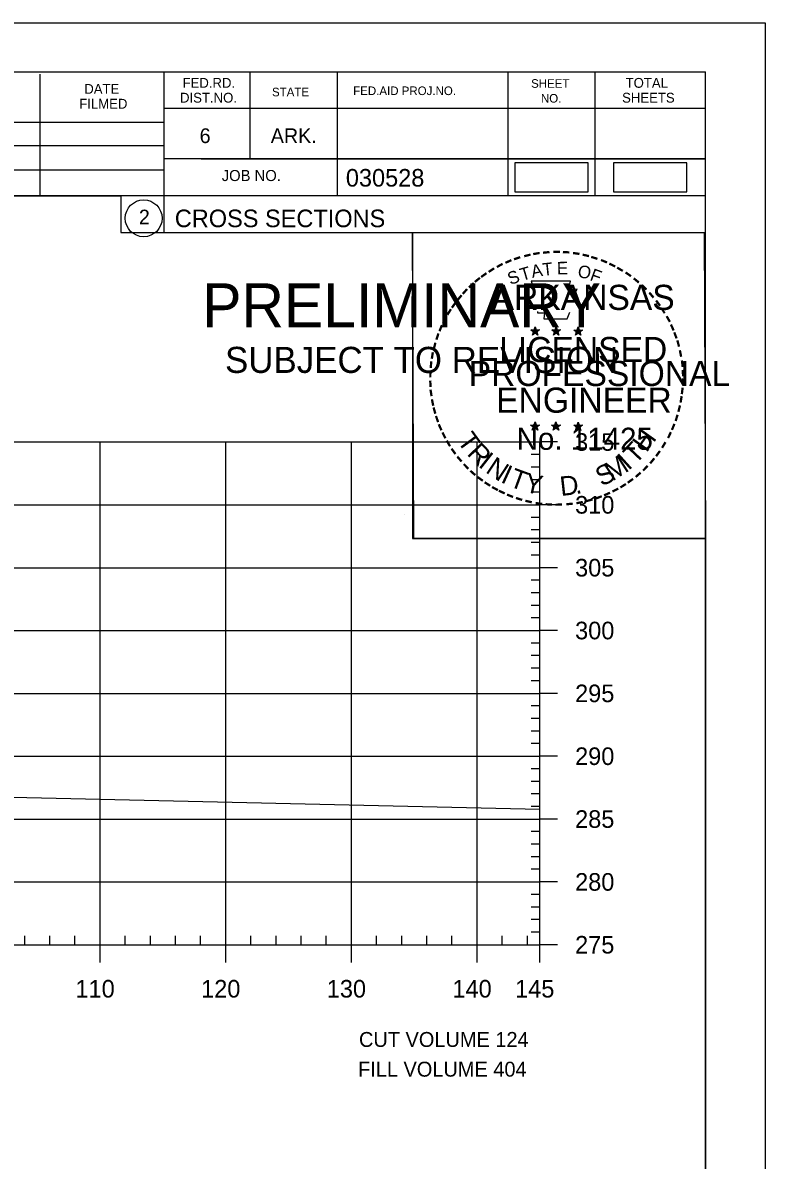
# Model space of a CAD drawing. Extents: x 1370843 to 1371177, y 380307 to 382654.
# Drawn here: x 1371117.6 to 1371176.6, y 380857 to 380947.5 of the extents above; entities that cross this region are included whole.
import ezdxf

# ---------------------------------------------------------------- set-up
doc = ezdxf.new("R2010")
doc.units = 0
for name, color, linetype in [('R_Axis', 7, 'Continuous'), ('R_Axis Annot', 7, 'Continuous'), ('R_Border', 7, 'Continuous'), ('R_Border Notes', 7, 'Continuous'), ('R_Border PE', 7, 'Continuous'), ('R_Border Prem', 7, 'Continuous'), ('R_Draft', 7, 'Continuous'), ('R_Exist Surface', 7, 'Continuous'), ('R_Grid', 7, 'Continuous'), ('R_No Plot', 7, 'Continuous')]:
    doc.layers.add(name, color=color, linetype=linetype)

msp = doc.modelspace()

# ---------------------------------------------------------------- linework, layer by layer
at = {"layer": 'R_Axis'}
for p, q in [((1371158.709, 380874.124), (1371158.709, 380914.124)), ((1371160.109, 380914.124), (1371158.709, 380914.124)), ((1371158.709, 380913.124), (1371158.009, 380913.124)), ((1371158.709, 380912.124), (1371158.009, 380912.124)), ((1371158.709, 380911.124), (1371158.009, 380911.124)), ((1371158.709, 380910.124), (1371158.009, 380910.124)), ((1371160.109, 380909.124), (1371158.709, 380909.124)), ((1371158.709, 380908.124), (1371158.009, 380908.124)), ((1371158.709, 380907.124), (1371158.009, 380907.124)), ((1371158.709, 380906.124), (1371158.009, 380906.124)), ((1371158.709, 380905.124), (1371158.009, 380905.124)), ((1371160.109, 380904.124), (1371158.709, 380904.124)), ((1371158.709, 380903.124), (1371158.009, 380903.124)), ((1371158.709, 380902.124), (1371158.009, 380902.124)), ((1371158.709, 380901.124), (1371158.009, 380901.124)), ((1371158.709, 380900.124), (1371158.009, 380900.124)), ((1371160.109, 380899.124), (1371158.709, 380899.124)), ((1371158.709, 380898.124), (1371158.009, 380898.124)), ((1371158.709, 380897.124), (1371158.009, 380897.124)), ((1371158.709, 380896.124), (1371158.009, 380896.124)), ((1371158.709, 380895.124), (1371158.009, 380895.124)), ((1371160.109, 380894.124), (1371158.709, 380894.124)), ((1371158.709, 380893.124), (1371158.009, 380893.124)), ((1371158.709, 380892.124), (1371158.009, 380892.124)), ((1371158.709, 380891.124), (1371158.009, 380891.124)), ((1371158.709, 380890.124), (1371158.009, 380890.124)), ((1371160.109, 380889.124), (1371158.709, 380889.124)), ((1371158.709, 380888.124), (1371158.009, 380888.124)), ((1371158.709, 380887.124), (1371158.009, 380887.124)), ((1371158.709, 380886.124), (1371158.009, 380886.124)), ((1371158.709, 380885.124), (1371158.009, 380885.124)), ((1371160.109, 380884.124), (1371158.709, 380884.124)), ((1371158.709, 380883.124), (1371158.009, 380883.124)), ((1371158.709, 380882.124), (1371158.009, 380882.124)), ((1371158.709, 380881.124), (1371158.009, 380881.124)), ((1371158.709, 380880.124), (1371158.009, 380880.124)), ((1371160.109, 380879.124), (1371158.709, 380879.124)), ((1371158.709, 380878.124), (1371158.009, 380878.124)), ((1371158.709, 380877.124), (1371158.009, 380877.124)), ((1371158.709, 380876.124), (1371158.009, 380876.124)), ((1371117.709, 380874.124), (1371117.709, 380874.824)), ((1371119.709, 380874.124), (1371119.709, 380874.824)), ((1371121.709, 380874.124), (1371121.709, 380874.824)), ((1371125.709, 380874.124), (1371125.709, 380874.824)), ((1371127.709, 380874.124), (1371127.709, 380874.824)), ((1371129.709, 380874.124), (1371129.709, 380874.824)), ((1371131.709, 380874.124), (1371131.709, 380874.824)), ((1371135.709, 380874.124), (1371135.709, 380874.824)), ((1371137.709, 380874.124), (1371137.709, 380874.824)), ((1371139.709, 380874.124), (1371139.709, 380874.824)), ((1371141.709, 380874.124), (1371141.709, 380874.824)), ((1371145.709, 380874.124), (1371145.709, 380874.824)), ((1371147.709, 380874.124), (1371147.709, 380874.824)), ((1371149.709, 380874.124), (1371149.709, 380874.824)), ((1371151.709, 380874.124), (1371151.709, 380874.824)), ((1371155.709, 380874.124), (1371155.709, 380874.824)), ((1371157.709, 380874.124), (1371157.709, 380874.824)), ((1371158.709, 380875.124), (1371158.009, 380875.124)), ((1370868.709, 380874.124), (1371158.709, 380874.124)), ((1371123.709, 380872.724), (1371123.709, 380874.124)), ((1371133.709, 380872.724), (1371133.709, 380874.124)), ((1371143.709, 380872.724), (1371143.709, 380874.124)), ((1371153.709, 380872.724), (1371153.709, 380874.124)), ((1371158.709, 380872.724), (1371158.709, 380874.124)), ((1371160.109, 380874.124), (1371158.709, 380874.124))]:
    msp.add_line(p, q, dxfattribs=at)
at = {"layer": 'R_Border'}
for p, q in [((1370855.709, 380943.584), (1371171.889, 380943.584)), ((1371128.789, 380943.584), (1371128.789, 380930.784)), ((1371135.629, 380943.584), (1371135.629, 380936.644)), ((1371142.569, 380943.584), (1371142.569, 380933.704)), ((1371156.149, 380943.584), (1371156.149, 380933.704)), ((1371163.089, 380943.584), (1371163.089, 380933.704)), ((1371171.889, 380738.124), (1371171.889, 380943.584)), ((1371118.929, 380933.704), (1371118.929, 380943.384)), ((1371171.889, 380940.644), (1371128.789, 380940.644)), ((1371171.889, 380940.664), (1371171.889, 380940.664)), ((1371089.629, 380939.564), (1371128.789, 380939.564)), ((1371089.629, 380937.704), (1371128.789, 380937.704)), ((1371171.889, 380936.644), (1371128.789, 380936.644)), ((1371131.749, 380936.644), (1371171.889, 380936.644)), ((1371089.629, 380935.764), (1371128.789, 380935.764)), ((1371171.889, 380933.704), (1371089.629, 380933.704)), ((1371128.789, 380930.784), (1371171.889, 380930.784))]:
    msp.add_line(p, q, dxfattribs=at)
msp.add_circle((1371127.176, 380931.92), 1.467, dxfattribs=at)
at = {"layer": 'R_Border PE'}
for p, q in [((1371157.974, 380923.039), (1371158.323, 380922.928)), ((1371157.974, 380923.039), (1371158.227, 380922.994)), ((1371157.974, 380923.039), (1371158.211, 380922.917)), ((1371158.107, 380922.631), (1371158.323, 380922.928)), ((1371158.107, 380922.631), (1371158.233, 380922.875)), ((1371158.107, 380922.631), (1371158.321, 380922.848)), ((1371158.323, 380923.293), (1371158.282, 380923.041)), ((1371158.536, 380922.631), (1371158.321, 380922.845)), ((1371158.323, 380922.928), (1371158.323, 380923.293)), ((1371158.323, 380923.293), (1371158.372, 380923.043)), ((1371158.67, 380923.039), (1371158.323, 380922.928)), ((1371158.536, 380922.631), (1371158.323, 380922.928)), ((1371158.67, 380923.039), (1371158.384, 380922.99)), ((1371158.536, 380922.631), (1371158.399, 380922.922)), ((1371158.67, 380923.039), (1371158.466, 380922.937)), ((1371159.644, 380923.039), (1371159.993, 380922.928)), ((1371159.644, 380923.039), (1371159.897, 380922.994)), ((1371159.644, 380923.039), (1371159.881, 380922.917)), ((1371159.777, 380922.631), (1371159.993, 380922.928)), ((1371159.777, 380922.631), (1371159.903, 380922.875)), ((1371159.777, 380922.631), (1371159.991, 380922.848)), ((1371159.993, 380923.293), (1371159.952, 380923.041)), ((1371160.206, 380922.631), (1371159.991, 380922.845)), ((1371159.993, 380922.928), (1371159.993, 380923.293)), ((1371159.993, 380923.293), (1371160.042, 380923.043)), ((1371160.34, 380923.039), (1371159.993, 380922.928)), ((1371160.206, 380922.631), (1371159.993, 380922.928)), ((1371160.34, 380923.039), (1371160.054, 380922.99)), ((1371160.206, 380922.631), (1371160.069, 380922.922)), ((1371160.34, 380923.039), (1371160.136, 380922.937)), ((1371161.408, 380923.027), (1371161.757, 380922.916)), ((1371161.408, 380923.027), (1371161.661, 380922.982)), ((1371161.408, 380923.027), (1371161.645, 380922.905)), ((1371161.541, 380922.619), (1371161.757, 380922.916)), ((1371161.541, 380922.619), (1371161.667, 380922.863)), ((1371161.541, 380922.619), (1371161.755, 380922.836)), ((1371161.757, 380923.281), (1371161.716, 380923.029)), ((1371161.97, 380922.619), (1371161.755, 380922.833)), ((1371161.757, 380922.916), (1371161.757, 380923.281)), ((1371161.757, 380923.281), (1371161.806, 380923.031)), ((1371162.104, 380923.027), (1371161.757, 380922.916)), ((1371161.97, 380922.619), (1371161.757, 380922.916)), ((1371162.104, 380923.027), (1371161.818, 380922.978)), ((1371161.97, 380922.619), (1371161.833, 380922.91)), ((1371162.104, 380923.027), (1371161.9, 380922.925)), ((1371157.97, 380915.466), (1371158.319, 380915.355)), ((1371157.97, 380915.466), (1371158.223, 380915.421)), ((1371157.97, 380915.466), (1371158.207, 380915.344)), ((1371158.103, 380915.058), (1371158.319, 380915.355)), ((1371158.319, 380915.72), (1371158.278, 380915.468)), ((1371158.319, 380915.355), (1371158.319, 380915.72)), ((1371158.319, 380915.72), (1371158.368, 380915.47)), ((1371158.666, 380915.466), (1371158.319, 380915.355)), ((1371158.532, 380915.058), (1371158.319, 380915.355)), ((1371158.666, 380915.466), (1371158.38, 380915.417)), ((1371158.666, 380915.466), (1371158.462, 380915.364)), ((1371159.639, 380915.466), (1371159.988, 380915.355)), ((1371159.639, 380915.466), (1371159.892, 380915.421)), ((1371159.639, 380915.466), (1371159.876, 380915.344)), ((1371159.772, 380915.058), (1371159.988, 380915.355)), ((1371159.988, 380915.72), (1371159.947, 380915.468)), ((1371159.988, 380915.355), (1371159.988, 380915.72)), ((1371159.988, 380915.72), (1371160.037, 380915.47)), ((1371160.335, 380915.466), (1371159.988, 380915.355)), ((1371160.201, 380915.058), (1371159.988, 380915.355)), ((1371160.335, 380915.466), (1371160.049, 380915.417)), ((1371160.335, 380915.466), (1371160.131, 380915.364)), ((1371161.406, 380915.456), (1371161.755, 380915.345)), ((1371161.406, 380915.456), (1371161.659, 380915.411)), ((1371161.406, 380915.456), (1371161.643, 380915.334)), ((1371161.755, 380915.71), (1371161.714, 380915.458)), ((1371161.755, 380915.345), (1371161.755, 380915.71)), ((1371161.755, 380915.71), (1371161.804, 380915.46)), ((1371162.102, 380915.456), (1371161.755, 380915.345)), ((1371162.102, 380915.456), (1371161.816, 380915.407)), ((1371162.102, 380915.456), (1371161.898, 380915.354)), ((1371158.103, 380915.058), (1371158.229, 380915.302)), ((1371158.103, 380915.058), (1371158.317, 380915.275)), ((1371158.532, 380915.058), (1371158.317, 380915.272)), ((1371158.532, 380915.058), (1371158.395, 380915.349)), ((1371159.772, 380915.058), (1371159.898, 380915.302)), ((1371159.772, 380915.058), (1371159.986, 380915.275)), ((1371160.201, 380915.058), (1371159.986, 380915.272)), ((1371160.201, 380915.058), (1371160.064, 380915.349)), ((1371161.539, 380915.048), (1371161.755, 380915.345)), ((1371161.539, 380915.048), (1371161.665, 380915.292)), ((1371161.539, 380915.048), (1371161.753, 380915.265)), ((1371161.968, 380915.048), (1371161.753, 380915.262)), ((1371161.968, 380915.048), (1371161.755, 380915.345)), ((1371161.968, 380915.048), (1371161.831, 380915.339))]:
    msp.add_line(p, q, dxfattribs=at)
for points in [[(1371158.015, 380926.917), (1371158.284, 380926.09)], [(1371161.526, 380925.995), (1371161.668, 380926.279), (1371160.983, 380926.255), (1371161.131, 380926.917), (1371158.015, 380926.917)], [(1371158.507, 380924.494), (1371158.507, 380924.407), (1371159.07, 380924.388), (1371159.016, 380923.915), (1371160.886, 380923.915), (1371161.087, 380924.451)], [(1371158.323, 380923.293), (1371158.536, 380922.631), (1371157.974, 380923.039), (1371158.67, 380923.039), (1371158.107, 380922.631), (1371158.323, 380923.293)], [(1371159.993, 380923.293), (1371160.206, 380922.631), (1371159.644, 380923.039), (1371160.34, 380923.039), (1371159.777, 380922.631), (1371159.993, 380923.293)], [(1371161.757, 380923.281), (1371161.97, 380922.619), (1371161.408, 380923.027), (1371162.104, 380923.027), (1371161.541, 380922.619), (1371161.757, 380923.281)], [(1371158.319, 380915.72), (1371158.532, 380915.058), (1371157.97, 380915.466), (1371158.666, 380915.466), (1371158.103, 380915.058), (1371158.319, 380915.72)], [(1371159.988, 380915.72), (1371160.201, 380915.058), (1371159.639, 380915.466), (1371160.335, 380915.466), (1371159.772, 380915.058), (1371159.988, 380915.72)], [(1371161.755, 380915.71), (1371161.968, 380915.048), (1371161.406, 380915.456), (1371162.102, 380915.456), (1371161.539, 380915.048), (1371161.755, 380915.71)]]:
    msp.add_lwpolyline(points, dxfattribs=at)
for centre, radius in [((1371158.322, 380922.927), 0.172), ((1371158.322, 380922.927), 0.145), ((1371158.322, 380922.927), 0.116), ((1371158.322, 380922.927), 0.0991), ((1371158.322, 380922.927), 0.0747), ((1371158.322, 380922.927), 0.0495), ((1371158.322, 380922.927), 0.0296), ((1371159.992, 380922.927), 0.172), ((1371159.992, 380922.927), 0.145), ((1371159.992, 380922.927), 0.116), ((1371159.992, 380922.927), 0.0991), ((1371159.992, 380922.927), 0.0747), ((1371159.992, 380922.927), 0.0495), ((1371159.992, 380922.927), 0.0296), ((1371161.756, 380922.915), 0.172), ((1371161.756, 380922.915), 0.145), ((1371161.756, 380922.915), 0.116), ((1371161.756, 380922.915), 0.0991), ((1371161.756, 380922.915), 0.0747), ((1371161.756, 380922.915), 0.0495), ((1371161.756, 380922.915), 0.0296), ((1371158.318, 380915.354), 0.172), ((1371158.318, 380915.354), 0.145), ((1371158.318, 380915.354), 0.116), ((1371158.318, 380915.354), 0.0991), ((1371158.318, 380915.354), 0.0747), ((1371158.318, 380915.354), 0.0495), ((1371158.318, 380915.354), 0.0296), ((1371159.987, 380915.354), 0.172), ((1371159.987, 380915.354), 0.145), ((1371159.987, 380915.354), 0.116), ((1371159.987, 380915.354), 0.0991), ((1371159.987, 380915.354), 0.0747), ((1371159.987, 380915.354), 0.0495), ((1371159.987, 380915.354), 0.0296), ((1371161.754, 380915.344), 0.172), ((1371161.754, 380915.344), 0.145), ((1371161.754, 380915.344), 0.116), ((1371161.754, 380915.344), 0.0991), ((1371161.754, 380915.344), 0.0747), ((1371161.754, 380915.344), 0.0495), ((1371161.754, 380915.344), 0.0296)]:
    msp.add_circle(centre, radius, dxfattribs=at)
at = {"layer": 'R_Draft'}
for points in [[(1371156.702, 380934.019), (1371162.536, 380934.019), (1371162.536, 380936.329), (1371156.702, 380936.329)], [(1371164.572, 380934.019), (1371170.406, 380934.019), (1371170.406, 380936.329), (1371164.572, 380936.329)]]:
    msp.add_lwpolyline(points, close=True, dxfattribs=at)
at = {"layer": 'R_Exist Surface'}
msp.add_line((1371066.491, 380886.977), (1371158.705, 380884.921), dxfattribs=at)
at = {"layer": 'R_Grid'}
for p, q in [((1370868.709, 380914.124), (1371158.709, 380914.124)), ((1371123.709, 380874.124), (1371123.709, 380914.124)), ((1371133.709, 380874.124), (1371133.709, 380914.124)), ((1371143.709, 380874.124), (1371143.709, 380914.124)), ((1371153.709, 380874.124), (1371153.709, 380914.124)), ((1371158.709, 380874.124), (1371158.709, 380914.124)), ((1370868.709, 380909.124), (1371158.709, 380909.124)), ((1370868.709, 380904.124), (1371158.709, 380904.124)), ((1370868.709, 380899.124), (1371158.709, 380899.124)), ((1370868.709, 380894.124), (1371158.709, 380894.124)), ((1370868.709, 380889.124), (1371158.709, 380889.124)), ((1370868.709, 380884.124), (1371158.709, 380884.124)), ((1370868.709, 380879.124), (1371158.709, 380879.124)), ((1370868.709, 380874.124), (1371158.709, 380874.124))]:
    msp.add_line(p, q, dxfattribs=at)
at = {"layer": 'R_No Plot'}
for p, q in [((1370843.308, 380947.479), (1371176.642, 380947.479)), ((1371147.923, 380908.329), (1371147.923, 380908.329))]:
    msp.add_line(p, q, dxfattribs=at)
for points in [[(1370843.302, 380947.479), (1371176.642, 380947.479), (1371176.642, 380734.141), (1370843.302, 380734.141)], [(1371089.629, 380943.584), (1371089.629, 380933.704), (1371125.361, 380933.704), (1371125.361, 380930.784), (1371148.561, 380930.784), (1371148.561, 380906.452), (1371171.889, 380906.452), (1371171.889, 380738.124), (1370855.709, 380738.124), (1370855.709, 380943.584)], [(1371148.561, 380930.784), (1371171.768, 380930.784), (1371171.889, 380906.452), (1371148.681, 380906.452)]]:
    msp.add_lwpolyline(points, close=True, dxfattribs=at)

# ---------------------------------------------------------------- texts
at = {"layer": 'R_Axis Annot'}
for s, p in [('315', (1371161.509, 380913.424)), ('310', (1371161.509, 380908.424)), ('305', (1371161.509, 380903.424)), ('300', (1371161.509, 380898.424)), ('295', (1371161.509, 380893.424)), ('290', (1371161.509, 380888.424)), ('285', (1371161.509, 380883.424)), ('280', (1371161.509, 380878.424)), ('275', (1371161.509, 380873.424)), ('110', (1371121.748, 380869.924)), ('120', (1371131.748, 380869.924)), ('130', (1371141.748, 380869.924)), ('140', (1371151.748, 380869.924)), ('145', (1371156.735, 380869.924))]:
    msp.add_text(s, height=1.4, dxfattribs=at).set_placement(p)
at = {"layer": 'R_Border'}
for s, height, p in [('DATE', 0.7819, (1371122.449, 380941.824)), ('FED.RD.', 0.7819, (1371130.269, 380942.304)), ('SHEET', 0.684, (1371158.009, 380942.304)), ('TOTAL', 0.7819, (1371165.529, 380942.304)), ('DIST.NO.', 0.7819, (1371130.069, 380941.124)), ('STATE', 0.684, (1371137.389, 380941.624)), ('FED.AID PROJ.NO.', 0.684, (1371143.849, 380941.724)), ('NO.', 0.684, (1371158.789, 380941.124)), ('SHEETS', 0.7819, (1371165.249, 380941.124)), ('FILMED', 0.7819, (1371122.049, 380940.644)), ('6', 1.172, (1371131.629, 380937.904)), ('ARK.', 1.1723, (1371137.289, 380937.904)), ('JOB NO.', 0.8792, (1371133.389, 380934.884)), ('030528', 1.4, (1371143.265, 380934.444)), ('2', 1.172, (1371126.793, 380931.433)), ('CROSS SECTIONS', 1.4, (1371129.653, 380931.214))]:
    msp.add_text(s, height=height, rotation=360, dxfattribs=at).set_placement(p)
at = {"layer": 'R_Border Notes'}
for s, p in [('CUT VOLUME 124', (1371144.31, 380865.993)), ('FILL VOLUME 404', (1371144.235, 380863.63))]:
    msp.add_text(s, height=1.18747, dxfattribs=at).set_placement(p)
at = {"layer": 'R_Border PE'}
for s, height, rotation, p in [('-', 1.6, 13.63015, (1371157.513, 380928.285)), ('-', 1.6, 10.21935, (1371158.191, 380928.447)), ('-', 1.6, 5.89682, (1371158.92, 380928.557)), ('-', 1.6, 0.18623, (1371159.692, 380928.629)), ('-', 1.6, 357.74304, (1371160.415, 380928.616)), ('-', 1.6, 352.16172, (1371161.159, 380928.56)), ('-', 1.6, 347.20489, (1371161.878, 380928.446)), ('-', 1.6, 342.3362, (1371162.513, 380928.291)), ('-', 1.6, 34.06357, (1371154.899, 380927.088)), ('-', 1.6, 28.79182, (1371155.496, 380927.458)), ('-', 1.6, 24.30721, (1371156.129, 380927.775)), ('-', 1.6, 19.17608, (1371156.763, 380928.044)), ('T', 1, 16.4036, (1371157.284, 380926.926)), ('A', 1, 11.21318, (1371158.11, 380927.177)), ('T', 1, 6.02276, (1371158.959, 380927.343)), ('E', 1, 0.83234, (1371160.064, 380927.453)), ('O', 1, 350.4515, (1371161.668, 380927.243)), ('-', 1.6, 337.85509, (1371163.248, 380928.068)), ('-', 1.6, 334.12109, (1371163.879, 380927.797)), ('-', 1.6, 329.64089, (1371164.458, 380927.514)), ('-', 1.6, 38.95066, (1371153.845, 380926.315)), ('-', 1.6, 36.23174, (1371154.321, 380926.693)), ('S', 1, 21.59401, (1371156.37, 380926.595)), ('F', 1, 340.07066, (1371162.622, 380927.015)), ('-', 1.6, 325.86266, (1371165.101, 380927.153)), ('-', 1.6, 320.52971, (1371165.711, 380926.727)), ('-', 1.6, 48.42305, (1371152.964, 380925.42)), ('-', 1.6, 42.96224, (1371153.412, 380925.898)), ('ARKANSAS', 2, 360, (1371154.868, 380924.629)), ('-', 1.6, 315.57859, (1371166.31, 380926.239)), ('-', 1.6, 50.61417, (1371152.561, 380924.934)), ('-', 1.6, 309.87973, (1371166.879, 380925.689)), ('-', 1.6, 306.65218, (1371167.404, 380925.087)), ('-', 1.6, 58.07063, (1371151.823, 380923.84)), ('-', 1.6, 54.23247, (1371152.148, 380924.367)), ('-', 1.4, 303.67529, (1371167.89, 380924.519)), ('-', 1.6, 62.87135, (1371151.51, 380923.226)), ('-', 1.6, 299.66835, (1371168.209, 380923.912)), ('-', 1.6, 294.66279, (1371168.533, 380923.3)), ('-', 1.6, 72.39447, (1371151.032, 380921.985)), ('-', 1.6, 67.77427, (1371151.251, 380922.615)), ('DWB', 0.01, 360, (1371158.31, 380922.923)), ('DWB', 0.01, 360, (1371159.98, 380922.923)), ('DWB', 0.01, 360, (1371161.744, 380922.912)), ('-', 1.6, 290.57283, (1371168.79, 380922.723)), ('-', 1.6, 75.46096, (1371150.835, 380921.271)), ('LICENSED', 2, 360, (1371155.465, 380920.48)), ('-', 1.6, 285.12326, (1371169.024, 380922.143)), ('-', 1.6, 81.20126, (1371150.703, 380920.558)), ('-', 1.6, 280.54934, (1371169.224, 380921.401)), ('-', 1.6, 85.18634, (1371150.627, 380919.867)), ('PROFESSIONAL', 2, 360, (1371153.042, 380918.576)), ('-', 1.6, 276.59616, (1371169.386, 380920.633)), ('-', 1.6, 94.19588, (1371150.637, 380918.441)), ('-', 1.6, 89.06224, (1371150.602, 380919.166)), ('-', 1.6, 274.33011, (1371169.446, 380919.911)), ('-', 1.6, 269.94067, (1371169.48, 380919.279)), ('-', 1.6, 98.94793, (1371150.709, 380917.774)), ('ENGINEER', 2, 360, (1371155.229, 380916.451)), ('-', 1.6, 263.5172, (1371169.461, 380918.613)), ('-', 1.6, 101.71495, (1371150.844, 380917.041)), ('-', 1.6, 260.99529, (1371169.39, 380917.959)), ('-', 1.6, 105.45785, (1371151.006, 380916.446)), ('-', 1.6, 252.86809, (1371169.099, 380916.561)), ('-', 1.6, 255.7626, (1371169.28, 380917.281)), ('-', 1.6, 109.08742, (1371151.221, 380915.815)), ('-', 1.6, 114.06432, (1371151.475, 380915.219)), ('DWB', 0.01, 360, (1371158.306, 380915.35)), ('DWB', 0.01, 360, (1371159.975, 380915.35)), ('-', 1.6, 247.88866, (1371168.876, 380915.888)), ('-', 1.6, 115.72885, (1371151.78, 380914.601)), ('T', 1.54, 306.04056, (1371152.078, 380914.193)), ('No. 11425', 1.757, 360, (1371156.856, 380913.5)), ('DWB', 0.01, 360, (1371161.742, 380915.34)), ('H', 1.54, 54.60883, (1371167.199, 380913.229)), ('-', 1.6, 244.61971, (1371168.614, 380915.259)), ('-', 1.6, 120.44712, (1371152.137, 380914.015)), ('-', 1.6, 125.89344, (1371152.54, 380913.454)), ('R', 1.54, 314.00497, (1371152.841, 380913.146)), ('T', 1.54, 46.64442, (1371166.309, 380912.286)), ('-', 1.6, 239.07125, (1371168.22, 380914.507)), ('-', 1.6, 130.71812, (1371153.002, 380912.902)), ('I', 1.54, 321.96938, (1371153.741, 380912.214)), ('N', 1.54, 326.50021, (1371154.309, 380911.742)), ('M', 1.54, 32.65632, (1371164.463, 380910.961)), ('I', 1.54, 42.11359, (1371165.747, 380911.808)), ('-', 1.6, 231.25377, (1371167.388, 380913.288)), ('-', 1.6, 233.84524, (1371167.818, 380913.854)), ('-', 1.6, 134.22381, (1371153.519, 380912.357)), ('-', 1.6, 138.93382, (1371154.044, 380911.893)), ('I', 1.54, 335.36034, (1371155.517, 380910.956)), ('T', 1.54, 339.89117, (1371156.178, 380910.629)), ('S', 1.54, 26.9312, (1371163.624, 380910.555)), ('-', 1.6, 221.08509, (1371166.387, 380912.215)), ('-', 1.6, 225.76533, (1371166.909, 380912.724)), ('-', 1.6, 144.64634, (1371154.6, 380911.487)), ('-', 1.6, 148.08978, (1371155.161, 380911.116)), ('Y', 1.54, 347.85558, (1371157.395, 380910.183)), ('D', 1.54, 6.39691, (1371160.38, 380909.825)), ('-', 1.6, 212.24909, (1371165.304, 380911.356)), ('-', 1.6, 215.73633, (1371165.838, 380911.743)), ('-', 1.6, 151.57039, (1371155.74, 380910.791)), ('-', 1.6, 154.60019, (1371156.262, 380910.544)), ('-', 1.6, 158.56121, (1371156.886, 380910.29)), ('.', 1.54, 13.76417, (1371161.572, 380909.952)), ('-', 1.6, 204.25161, (1371164.122, 380910.691)), ('-', 1.6, 207.35684, (1371164.746, 380911.01)), ('-', 1.6, 162.79826, (1371157.573, 380910.077)), ('-', 1.6, 167.55551, (1371158.288, 380909.913)), ('-', 1.6, 173.11546, (1371159.06, 380909.803)), ('-', 1.6, 176.51827, (1371159.808, 380909.75)), ('-', 1.6, 181.59176, (1371160.552, 380909.769)), ('-', 1.6, 185.81666, (1371161.361, 380909.845)), ('-', 1.6, 191.28576, (1371162.097, 380909.977)), ('-', 1.6, 195.47429, (1371162.826, 380910.176)), ('-', 1.6, 200.71842, (1371163.503, 380910.418))]:
    msp.add_text(s, height=height, rotation=rotation, dxfattribs=at).set_placement(p)
at = {"layer": 'R_Border Prem'}
for s, height, p in [('PRELIMINARY', 3.5, (1371131.84, 380923.247)), ('DWB', 0.01, (1371132.587, 380925.096)), ('SUBJECT TO REVISION', 2.07511, (1371133.649, 380919.618))]:
    msp.add_text(s, height=height, rotation=360, dxfattribs=at).set_placement(p)

doc.saveas('drawing.dxf')
